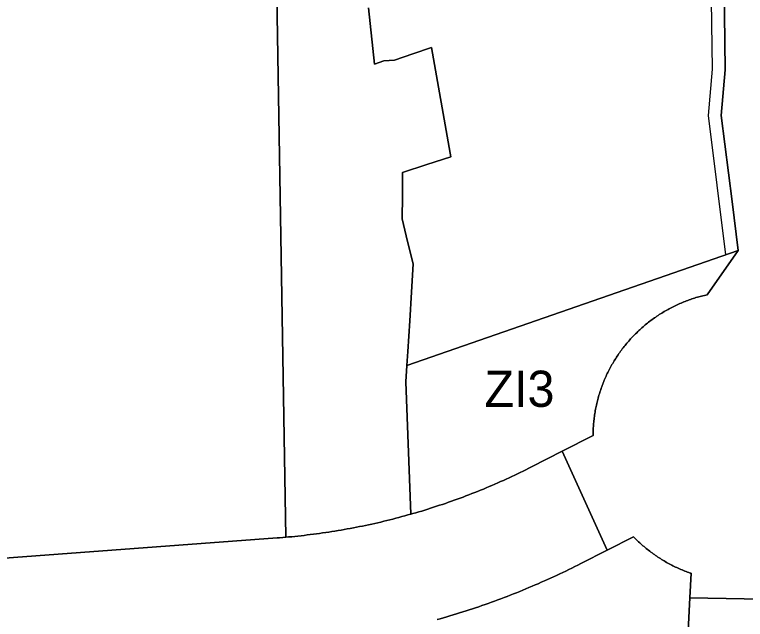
# Model space of a CAD drawing. Extents: x 7439486 to 7443435, y 5551288 to 5554556.
# Drawn here: x 7440595.5 to 7440797.2, y 5552066.8 to 5552233.9 of the extents above; entities that cross this region are included whole.
import ezdxf

# ---------------------------------------------------------------- set-up
doc = ezdxf.new("R2010")
doc.units = 0
for name, color, linetype in [('linie_rozgraniczajace', 7, 'Continuous'), ('linie_zabudowy_nieprzekraczalne', 7, 'Continuous'), ('oznaczenia_przeznaczen', 7, 'Continuous')]:
    doc.layers.add(name, color=color, linetype=linetype)

msp = doc.modelspace()

# ---------------------------------------------------------------- linework, layer by layer
at = {"layer": 'linie_rozgraniczajace'}
for points in [[(7440667.55, 5552255.86), (7440670.36, 5552089.49), (7440669.51, 5552089.42), (7440668.65, 5552089.35), (7440667.99, 5552089.3), (7440567.97, 5552081.84)], [(7440693.2, 5552235.79), (7440694.88, 5552220.22), (7440697.45, 5552221.11), (7440698.89, 5552221.24), (7440700.34, 5552221.37), (7440705.46, 5552223.1), (7440710.59, 5552224.84), (7440715.76, 5552195.65), (7440715.95, 5552194.6), (7440709.28, 5552192.46), (7440702.61, 5552190.32), (7440702.53, 5552183.88), (7440702.45, 5552177.45), (7440703.99, 5552171.26), (7440705.53, 5552165.08), (7440705.04, 5552157.19), (7440704.55, 5552149.31), (7440704.03, 5552140.85), (7440703.78, 5552136.94), (7440703.5, 5552132.39), (7440704.91, 5552095.87), (7440704.08, 5552095.64), (7440703.25, 5552095.41), (7440702.42, 5552095.18), (7440701.59, 5552094.96), (7440700.75, 5552094.74), (7440699.92, 5552094.52), (7440699.09, 5552094.31), (7440698.25, 5552094.11), (7440697.42, 5552093.9), (7440696.58, 5552093.7), (7440695.74, 5552093.51), (7440694.9, 5552093.32), (7440694.06, 5552093.13), (7440693.22, 5552092.95), (7440692.38, 5552092.77), (7440691.54, 5552092.59), (7440690.69, 5552092.42), (7440689.85, 5552092.25), (7440689.01, 5552092.09), (7440688.16, 5552091.93), (7440687.31, 5552091.77), (7440686.47, 5552091.62), (7440685.62, 5552091.47), (7440684.77, 5552091.33), (7440683.92, 5552091.19), (7440683.07, 5552091.05), (7440682.22, 5552090.92), (7440681.37, 5552090.79), (7440680.52, 5552090.67), (7440679.67, 5552090.55), (7440678.82, 5552090.43), (7440677.96, 5552090.32), (7440677.11, 5552090.21), (7440676.26, 5552090.11), (7440675.4, 5552090.01), (7440674.55, 5552089.91), (7440673.69, 5552089.82), (7440672.83, 5552089.73), (7440671.98, 5552089.64), (7440671.12, 5552089.56), (7440670.36, 5552089.49), (7440667.55, 5552255.86)], [(7440791.26, 5552249.64), (7440791.68, 5552218.68), (7440790.55, 5552206.06), (7440793.55, 5552182.26), (7440795.26, 5552168.69), (7440703.78, 5552136.94), (7440704.03, 5552140.85), (7440704.55, 5552149.31), (7440705.04, 5552157.19), (7440705.53, 5552165.08), (7440703.99, 5552171.26), (7440702.45, 5552177.45), (7440702.53, 5552183.88), (7440702.61, 5552190.32), (7440709.28, 5552192.46), (7440715.95, 5552194.6), (7440715.76, 5552195.65), (7440710.59, 5552224.84), (7440705.46, 5552223.1), (7440700.34, 5552221.37), (7440698.89, 5552221.24), (7440697.45, 5552221.11), (7440694.88, 5552220.22), (7440693.2, 5552235.79)], [(7440777.64, 5552153.37), (7440778.01, 5552153.54), (7440778.37, 5552153.71), (7440778.73, 5552153.88), (7440779.1, 5552154.04), (7440779.46, 5552154.2), (7440779.83, 5552154.35), (7440780.2, 5552154.5), (7440780.57, 5552154.65), (7440780.95, 5552154.8), (7440781.32, 5552154.94), (7440781.7, 5552155.07), (7440782.08, 5552155.21), (7440782.45, 5552155.34), (7440782.83, 5552155.46), (7440783.22, 5552155.58), (7440783.6, 5552155.7), (7440783.98, 5552155.82), (7440784.37, 5552155.93), (7440784.75, 5552156.03), (7440785.14, 5552156.13), (7440785.53, 5552156.23), (7440785.91, 5552156.33), (7440786.3, 5552156.42), (7440786.7, 5552156.51), (7440795.26, 5552168.69), (7440793.55, 5552182.26), (7440790.55, 5552206.06), (7440791.68, 5552218.68), (7440791.26, 5552249.64)], [(7440704.91, 5552095.87), (7440703.5, 5552132.39), (7440703.78, 5552136.94), (7440795.26, 5552168.69), (7440786.7, 5552156.51), (7440786.3, 5552156.42), (7440785.91, 5552156.33), (7440785.53, 5552156.23), (7440785.14, 5552156.13), (7440784.75, 5552156.03), (7440784.37, 5552155.93), (7440783.98, 5552155.82), (7440783.6, 5552155.7), (7440783.22, 5552155.58), (7440782.83, 5552155.46), (7440782.45, 5552155.34), (7440782.08, 5552155.21), (7440781.7, 5552155.07), (7440781.32, 5552154.94), (7440780.95, 5552154.8), (7440780.57, 5552154.65), (7440780.2, 5552154.5), (7440779.83, 5552154.35), (7440779.46, 5552154.2), (7440779.1, 5552154.04), (7440778.73, 5552153.88), (7440778.37, 5552153.71), (7440778.01, 5552153.54), (7440777.64, 5552153.37), (7440777.29, 5552153.19), (7440776.93, 5552153.01), (7440776.57, 5552152.82), (7440776.22, 5552152.64), (7440775.87, 5552152.44), (7440775.52, 5552152.25), (7440775.17, 5552152.05), (7440774.83, 5552151.85), (7440774.48, 5552151.64), (7440774.14, 5552151.44), (7440773.8, 5552151.22), (7440773.47, 5552151.01), (7440773.13, 5552150.79), (7440772.8, 5552150.57), (7440772.47, 5552150.34), (7440772.14, 5552150.11), (7440771.81, 5552149.88), (7440771.49, 5552149.64), (7440771.17, 5552149.41), (7440770.85, 5552149.16), (7440770.53, 5552148.92), (7440770.22, 5552148.67), (7440769.91, 5552148.42), (7440769.6, 5552148.17), (7440769.29, 5552147.91), (7440768.99, 5552147.65), (7440768.69, 5552147.39), (7440768.39, 5552147.12), (7440768.09, 5552146.85), (7440767.8, 5552146.58), (7440767.51, 5552146.3), (7440767.22, 5552146.02), (7440766.94, 5552145.74), (7440766.66, 5552145.46), (7440766.38, 5552145.17), (7440766.1, 5552144.88), (7440765.83, 5552144.59), (7440765.56, 5552144.29), (7440765.29, 5552144), (7440765.03, 5552143.7), (7440764.76, 5552143.39), (7440764.51, 5552143.09), (7440764.25, 5552142.78), (7440764, 5552142.47), (7440763.75, 5552142.16), (7440763.5, 5552141.84), (7440763.26, 5552141.52), (7440763.02, 5552141.2), (7440762.78, 5552140.88), (7440762.55, 5552140.56), (7440762.32, 5552140.23), (7440762.09, 5552139.9), (7440761.87, 5552139.57), (7440761.65, 5552139.23), (7440761.43, 5552138.9), (7440761.22, 5552138.56), (7440761.01, 5552138.22), (7440760.81, 5552137.87), (7440760.6, 5552137.53), (7440760.4, 5552137.18), (7440760.21, 5552136.83), (7440760.01, 5552136.48), (7440759.83, 5552136.13), (7440759.64, 5552135.78), (7440759.46, 5552135.42), (7440759.28, 5552135.06), (7440759.1, 5552134.7), (7440758.93, 5552134.34), (7440758.77, 5552133.98), (7440758.6, 5552133.61), (7440758.44, 5552133.25)], [(7440755.49, 5552122.48), (7440755.55, 5552122.87), (7440755.6, 5552123.27), (7440755.66, 5552123.66), (7440755.73, 5552124.06), (7440755.8, 5552124.45), (7440755.87, 5552124.85), (7440755.95, 5552125.24), (7440756.03, 5552125.63), (7440756.11, 5552126.02), (7440756.2, 5552126.41), (7440756.29, 5552126.8), (7440756.39, 5552127.19), (7440756.49, 5552127.58), (7440756.59, 5552127.96), (7440756.7, 5552128.35), (7440756.81, 5552128.73), (7440756.92, 5552129.12), (7440757.04, 5552129.5), (7440757.17, 5552129.88), (7440757.29, 5552130.26), (7440757.42, 5552130.64), (7440757.56, 5552131.01), (7440757.7, 5552131.39), (7440757.84, 5552131.76), (7440757.98, 5552132.14), (7440758.13, 5552132.51), (7440758.29, 5552132.88), (7440758.44, 5552133.25), (7440758.6, 5552133.61), (7440758.77, 5552133.98), (7440758.93, 5552134.34), (7440759.1, 5552134.7), (7440759.28, 5552135.06), (7440759.46, 5552135.42), (7440759.64, 5552135.78), (7440759.83, 5552136.13), (7440760.01, 5552136.48), (7440760.21, 5552136.83), (7440760.4, 5552137.18), (7440760.6, 5552137.53), (7440760.81, 5552137.87), (7440761.01, 5552138.22), (7440761.22, 5552138.56), (7440761.43, 5552138.9), (7440761.65, 5552139.23), (7440761.87, 5552139.57), (7440762.09, 5552139.9), (7440762.32, 5552140.23), (7440762.55, 5552140.56), (7440762.78, 5552140.88), (7440763.02, 5552141.2), (7440763.26, 5552141.52), (7440763.5, 5552141.84), (7440763.75, 5552142.16), (7440764, 5552142.47), (7440764.25, 5552142.78), (7440764.51, 5552143.09), (7440764.76, 5552143.39), (7440765.03, 5552143.7), (7440765.29, 5552144), (7440765.56, 5552144.29), (7440765.83, 5552144.59), (7440766.1, 5552144.88), (7440766.38, 5552145.17), (7440766.66, 5552145.46), (7440766.94, 5552145.74), (7440767.22, 5552146.02), (7440767.51, 5552146.3), (7440767.8, 5552146.58), (7440768.09, 5552146.85), (7440768.39, 5552147.12), (7440768.69, 5552147.39), (7440768.99, 5552147.65), (7440769.29, 5552147.91), (7440769.6, 5552148.17), (7440769.91, 5552148.42), (7440770.22, 5552148.67), (7440770.53, 5552148.92), (7440770.85, 5552149.16), (7440771.17, 5552149.41), (7440771.49, 5552149.64), (7440771.81, 5552149.88), (7440772.14, 5552150.11), (7440772.47, 5552150.34), (7440772.8, 5552150.57), (7440773.13, 5552150.79), (7440773.47, 5552151.01), (7440773.8, 5552151.22), (7440774.14, 5552151.44), (7440774.48, 5552151.64), (7440774.83, 5552151.85), (7440775.17, 5552152.05), (7440775.52, 5552152.25), (7440775.87, 5552152.44), (7440776.22, 5552152.64), (7440776.57, 5552152.82), (7440776.93, 5552153.01), (7440777.29, 5552153.19), (7440777.64, 5552153.37)], [(7440758.44, 5552133.25), (7440758.29, 5552132.88), (7440758.13, 5552132.51), (7440757.98, 5552132.14), (7440757.84, 5552131.76), (7440757.7, 5552131.39), (7440757.56, 5552131.01), (7440757.42, 5552130.64), (7440757.29, 5552130.26), (7440757.17, 5552129.88), (7440757.04, 5552129.5), (7440756.92, 5552129.12), (7440756.81, 5552128.73), (7440756.7, 5552128.35), (7440756.59, 5552127.96), (7440756.49, 5552127.58), (7440756.39, 5552127.19), (7440756.29, 5552126.8), (7440756.2, 5552126.41), (7440756.11, 5552126.02), (7440756.03, 5552125.63), (7440755.95, 5552125.24), (7440755.87, 5552124.85), (7440755.8, 5552124.45), (7440755.73, 5552124.06), (7440755.66, 5552123.66), (7440755.6, 5552123.27), (7440755.55, 5552122.87), (7440755.49, 5552122.48), (7440755.44, 5552122.08), (7440755.4, 5552121.68), (7440755.36, 5552121.28), (7440755.32, 5552120.88), (7440755.29, 5552120.49), (7440755.26, 5552120.09), (7440755.23, 5552119.69), (7440755.21, 5552119.29), (7440755.2, 5552118.89), (7440755.18, 5552118.49), (7440755.18, 5552118.09), (7440755.17, 5552117.69), (7440755.17, 5552117.59), (7440746.67, 5552113.26), (7440738.17, 5552108.93), (7440737.41, 5552108.55), (7440736.64, 5552108.16), (7440735.86, 5552107.78), (7440735.09, 5552107.4), (7440734.32, 5552107.03), (7440733.54, 5552106.66), (7440732.76, 5552106.29), (7440731.98, 5552105.93), (7440731.2, 5552105.57), (7440730.42, 5552105.21), (7440729.63, 5552104.86), (7440728.85, 5552104.51), (7440728.06, 5552104.16), (7440727.27, 5552103.82), (7440726.48, 5552103.48), (7440725.68, 5552103.15), (7440724.89, 5552102.82), (7440724.09, 5552102.49), (7440723.3, 5552102.17), (7440722.5, 5552101.85), (7440721.7, 5552101.54), (7440720.89, 5552101.22), (7440720.09, 5552100.91), (7440719.29, 5552100.61), (7440718.48, 5552100.31), (7440717.67, 5552100.01), (7440716.86, 5552099.72), (7440716.05, 5552099.43), (7440715.24, 5552099.14), (7440714.43, 5552098.86), (7440713.61, 5552098.58), (7440712.8, 5552098.31), (7440711.98, 5552098.04), (7440711.16, 5552097.77), (7440710.34, 5552097.51), (7440709.52, 5552097.25), (7440708.7, 5552096.99), (7440707.88, 5552096.74), (7440707.06, 5552096.5), (7440706.23, 5552096.25), (7440705.4, 5552096.01), (7440704.91, 5552095.87)], [(7440806.89, 5552072.31), (7440781.88, 5552072.73), (7440782.23, 5552079.52), (7440782.03, 5552079.59), (7440781.65, 5552079.72), (7440781.27, 5552079.86), (7440780.9, 5552080), (7440780.53, 5552080.14), (7440780.16, 5552080.29), (7440779.79, 5552080.44), (7440779.42, 5552080.6), (7440779.05, 5552080.76), (7440778.69, 5552080.92), (7440778.32, 5552081.09), (7440777.96, 5552081.26), (7440777.6, 5552081.43), (7440777.24, 5552081.61), (7440776.89, 5552081.79), (7440776.53, 5552081.97), (7440776.18, 5552082.16), (7440775.83, 5552082.35), (7440775.48, 5552082.55), (7440775.13, 5552082.74), (7440774.79, 5552082.95), (7440774.45, 5552083.15), (7440774.1, 5552083.36), (7440773.77, 5552083.57), (7440773.43, 5552083.79), (7440773.1, 5552084.01), (7440772.76, 5552084.23), (7440772.43, 5552084.45), (7440772.11, 5552084.68), (7440771.78, 5552084.92), (7440771.46, 5552085.15), (7440771.14, 5552085.39), (7440770.82, 5552085.63), (7440770.5, 5552085.88), (7440770.19, 5552086.12), (7440769.88, 5552086.37), (7440769.57, 5552086.63), (7440769.26, 5552086.89), (7440768.96, 5552087.15), (7440768.66, 5552087.41), (7440768.36, 5552087.68), (7440768.07, 5552087.95), (7440767.77, 5552088.22), (7440767.49, 5552088.49), (7440767.2, 5552088.77), (7440766.91, 5552089.05), (7440766.63, 5552089.34), (7440766.35, 5552089.62), (7440759.07, 5552085.91), (7440746.67, 5552113.26), (7440755.17, 5552117.59), (7440755.17, 5552117.69), (7440755.18, 5552118.09), (7440755.18, 5552118.49), (7440755.2, 5552118.89), (7440755.21, 5552119.29), (7440755.23, 5552119.69), (7440755.26, 5552120.09), (7440755.29, 5552120.49), (7440755.32, 5552120.88), (7440755.36, 5552121.28), (7440755.4, 5552121.68), (7440755.44, 5552122.08), (7440755.49, 5552122.48)], [(7440710.34, 5552097.51), (7440711.16, 5552097.77), (7440711.98, 5552098.04), (7440712.8, 5552098.31), (7440713.61, 5552098.58), (7440714.43, 5552098.86), (7440715.24, 5552099.14), (7440716.05, 5552099.43), (7440716.86, 5552099.72), (7440717.67, 5552100.01), (7440718.48, 5552100.31), (7440719.29, 5552100.61), (7440720.09, 5552100.91), (7440720.89, 5552101.22), (7440721.7, 5552101.54), (7440722.5, 5552101.85), (7440723.3, 5552102.17), (7440724.09, 5552102.49), (7440724.89, 5552102.82), (7440725.68, 5552103.15), (7440726.48, 5552103.48), (7440727.27, 5552103.82), (7440728.06, 5552104.16), (7440728.85, 5552104.51), (7440729.63, 5552104.86), (7440730.42, 5552105.21), (7440731.2, 5552105.57), (7440731.98, 5552105.93), (7440732.76, 5552106.29), (7440733.54, 5552106.66), (7440734.32, 5552107.03), (7440735.09, 5552107.4), (7440735.86, 5552107.78), (7440736.64, 5552108.16), (7440737.41, 5552108.55), (7440738.17, 5552108.93), (7440746.67, 5552113.26), (7440759.07, 5552085.91), (7440751.79, 5552082.2), (7440750.96, 5552081.78), (7440750.13, 5552081.37), (7440749.3, 5552080.96), (7440748.47, 5552080.55), (7440747.63, 5552080.14), (7440746.8, 5552079.74), (7440745.96, 5552079.35), (7440745.12, 5552078.95), (7440744.28, 5552078.56), (7440743.43, 5552078.18), (7440742.59, 5552077.79), (7440741.74, 5552077.41), (7440740.89, 5552077.04), (7440740.04, 5552076.66), (7440739.19, 5552076.3), (7440738.34, 5552075.93), (7440737.49, 5552075.57), (7440736.63, 5552075.21), (7440735.77, 5552074.86), (7440734.92, 5552074.51), (7440734.05, 5552074.16), (7440733.19, 5552073.82), (7440732.33, 5552073.48), (7440731.47, 5552073.15), (7440730.6, 5552072.82), (7440729.73, 5552072.49), (7440728.86, 5552072.16), (7440727.99, 5552071.84), (7440727.12, 5552071.53), (7440726.25, 5552071.22), (7440725.37, 5552070.91), (7440724.5, 5552070.6), (7440723.62, 5552070.3), (7440722.74, 5552070), (7440721.86, 5552069.71), (7440720.98, 5552069.42), (7440720.1, 5552069.13), (7440719.22, 5552068.85), (7440718.33, 5552068.57), (7440717.44, 5552068.3), (7440716.56, 5552068.03), (7440715.67, 5552067.76), (7440714.78, 5552067.5), (7440713.89, 5552067.24), (7440713, 5552066.98), (7440712.11, 5552066.73)], [(7440567.97, 5552081.84), (7440667.99, 5552089.3), (7440668.65, 5552089.35), (7440669.51, 5552089.42), (7440670.36, 5552089.49), (7440671.12, 5552089.56), (7440671.98, 5552089.64), (7440672.83, 5552089.73), (7440673.69, 5552089.82), (7440674.55, 5552089.91), (7440675.4, 5552090.01), (7440676.26, 5552090.11), (7440677.11, 5552090.21), (7440677.96, 5552090.32), (7440678.82, 5552090.43), (7440679.67, 5552090.55), (7440680.52, 5552090.67), (7440681.37, 5552090.79), (7440682.22, 5552090.92), (7440683.07, 5552091.05), (7440683.92, 5552091.19), (7440684.77, 5552091.33), (7440685.62, 5552091.47), (7440686.47, 5552091.62), (7440687.31, 5552091.77), (7440688.16, 5552091.93), (7440689.01, 5552092.09), (7440689.85, 5552092.25), (7440690.69, 5552092.42), (7440691.54, 5552092.59), (7440692.38, 5552092.77), (7440693.22, 5552092.95), (7440694.06, 5552093.13), (7440694.9, 5552093.32), (7440695.74, 5552093.51), (7440696.58, 5552093.7), (7440697.42, 5552093.9), (7440698.25, 5552094.11), (7440699.09, 5552094.31), (7440699.92, 5552094.52), (7440700.75, 5552094.74), (7440701.59, 5552094.96), (7440702.42, 5552095.18), (7440703.25, 5552095.41), (7440704.08, 5552095.64), (7440704.91, 5552095.87), (7440705.4, 5552096.01), (7440706.23, 5552096.25), (7440707.06, 5552096.5), (7440707.88, 5552096.74), (7440708.7, 5552096.99), (7440709.52, 5552097.25), (7440710.34, 5552097.51)], [(7440712.11, 5552066.73), (7440713, 5552066.98), (7440713.89, 5552067.24), (7440714.78, 5552067.5), (7440715.67, 5552067.76), (7440716.56, 5552068.03), (7440717.44, 5552068.3), (7440718.33, 5552068.57), (7440719.22, 5552068.85), (7440720.1, 5552069.13), (7440720.98, 5552069.42), (7440721.86, 5552069.71), (7440722.74, 5552070), (7440723.62, 5552070.3), (7440724.5, 5552070.6), (7440725.37, 5552070.91), (7440726.25, 5552071.22), (7440727.12, 5552071.53), (7440727.99, 5552071.84), (7440728.86, 5552072.16), (7440729.73, 5552072.49), (7440730.6, 5552072.82), (7440731.47, 5552073.15), (7440732.33, 5552073.48), (7440733.19, 5552073.82), (7440734.05, 5552074.16), (7440734.92, 5552074.51), (7440735.77, 5552074.86), (7440736.63, 5552075.21), (7440737.49, 5552075.57), (7440738.34, 5552075.93), (7440739.19, 5552076.3), (7440740.04, 5552076.66), (7440740.89, 5552077.04), (7440741.74, 5552077.41), (7440742.59, 5552077.79), (7440743.43, 5552078.18), (7440744.28, 5552078.56), (7440745.12, 5552078.95), (7440745.96, 5552079.35), (7440746.8, 5552079.74), (7440747.63, 5552080.14), (7440748.47, 5552080.55), (7440749.3, 5552080.96), (7440750.13, 5552081.37), (7440750.96, 5552081.78), (7440751.79, 5552082.2), (7440759.07, 5552085.91), (7440766.35, 5552089.62), (7440766.63, 5552089.34)], [(7440766.63, 5552089.34), (7440766.91, 5552089.05), (7440767.2, 5552088.77), (7440767.49, 5552088.49), (7440767.77, 5552088.22), (7440768.07, 5552087.95), (7440768.36, 5552087.68), (7440768.66, 5552087.41), (7440768.96, 5552087.15), (7440769.26, 5552086.89), (7440769.57, 5552086.63), (7440769.88, 5552086.37), (7440770.19, 5552086.12), (7440770.5, 5552085.88), (7440770.82, 5552085.63), (7440771.14, 5552085.39), (7440771.46, 5552085.15), (7440771.78, 5552084.92), (7440772.11, 5552084.68), (7440772.43, 5552084.45), (7440772.76, 5552084.23), (7440773.1, 5552084.01), (7440773.43, 5552083.79), (7440773.77, 5552083.57), (7440774.1, 5552083.36), (7440774.45, 5552083.15), (7440774.79, 5552082.95), (7440775.13, 5552082.74), (7440775.48, 5552082.55), (7440775.83, 5552082.35), (7440776.18, 5552082.16), (7440776.53, 5552081.97), (7440776.89, 5552081.79), (7440777.24, 5552081.61), (7440777.6, 5552081.43), (7440777.96, 5552081.26), (7440778.32, 5552081.09), (7440778.69, 5552080.92), (7440779.05, 5552080.76), (7440779.42, 5552080.6), (7440779.79, 5552080.44), (7440780.16, 5552080.29), (7440780.53, 5552080.14), (7440780.9, 5552080), (7440781.27, 5552079.86), (7440781.65, 5552079.72), (7440782.03, 5552079.59), (7440782.23, 5552079.52), (7440781.88, 5552072.73), (7440774.18, 5551920.04)]]:
    msp.add_lwpolyline(points, dxfattribs=at)
msp.add_lwpolyline([(7440774.18, 5551920.04), (7440781.88, 5552072.73), (7440806.89, 5552072.31), (7440803.64, 5552007.76), (7440799.21, 5551920.11), (7440800.76, 5551892.23), (7440801.61, 5551877.02), (7440776.82, 5551882.03), (7440776.29, 5551882.14), (7440775.35, 5551899.06)], close=True, dxfattribs=at)
at = {"layer": 'linie_zabudowy_nieprzekraczalne'}
msp.add_lwpolyline([(7440791.88, 5552167.52), (7440787.03, 5552205.99), (7440788.18, 5552218.81), (7440787.69, 5552250.56), (7440779.98, 5552281.69), (7440765.06, 5552306.43), (7440755.26, 5552332.04), (7440745.45, 5552357.65), (7440734.06, 5552382.9), (7440722.7, 5552408.1), (7440716.68, 5552420.15), (7440711.39, 5552422.2), (7440695.35, 5552415.8)], dxfattribs=at)

# ---------------------------------------------------------------- texts
at = {"layer": 'oznaczenia_przeznaczen'}
msp.add_text('ZI3', height=10, dxfattribs=at).set_placement((7440725.2, 5552125.52))

doc.saveas('drawing.dxf')
